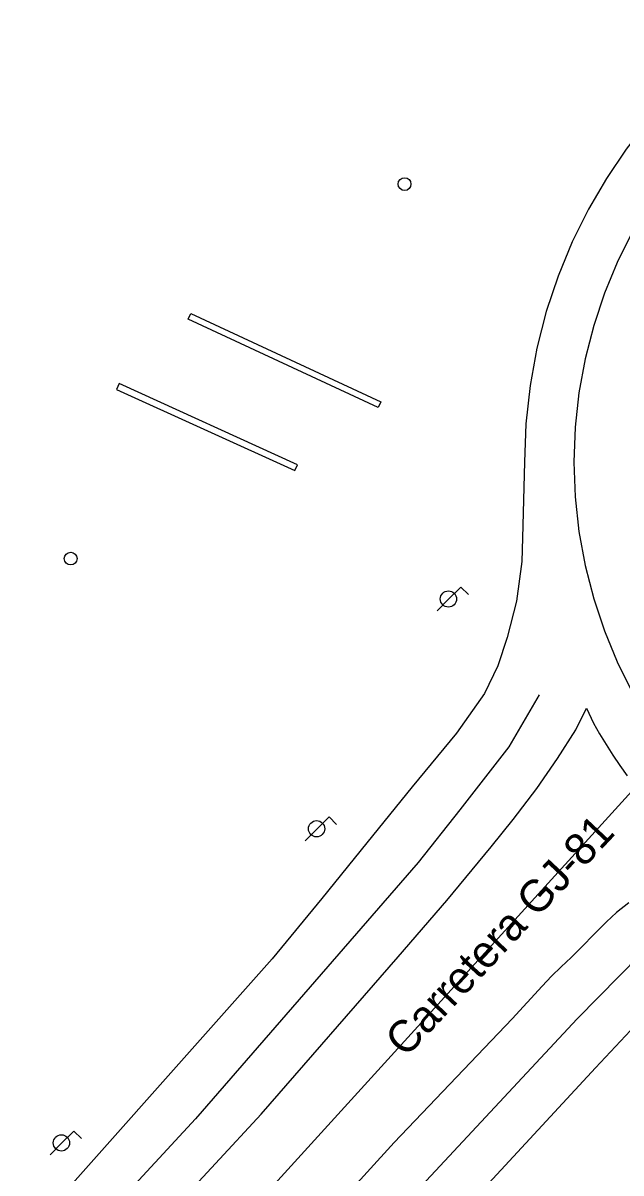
# Model space of a CAD drawing. Extents: x 282771 to 285132, y 4823109 to 4825496.
# Drawn here: x 283301 to 283347.9, y 4823498.7 to 4823588.9 of the extents above; entities that cross this region are included whole.
import ezdxf

# ---------------------------------------------------------------- set-up
doc = ezdxf.new("R2010")
doc.units = 0
for name, color, linetype in [('CALLE-EJE', 7, 'Continuous'), ('CALLE-TEXTO', 7, 'Continuous'), ('FAROLA', 7, 'Continuous'), ('POSTE', 7, 'Continuous'), ('PUENTE', 7, 'Continuous'), ('SENAL-VIARIA', 7, 'Continuous')]:
    doc.layers.add(name, color=color, linetype=linetype)

msp = doc.modelspace()

# ---------------------------------------------------------------- linework, layer by layer
at = {"layer": 'CALLE-EJE'}
msp.add_lwpolyline([(283294.286, 4823468.814), (283332.47, 4823510.781), (283376.815, 4823559.518)], dxfattribs=at)
at = {"layer": 'FAROLA'}
for p, q in [((283335.339, 4823544.653), (283334.399, 4823543.723)), ((283335.929, 4823544.063), (283335.339, 4823544.653)), ((283334.399, 4823543.723), (283333.469, 4823542.783)), ((283324.998, 4823526.639), (283324.058, 4823525.709)), ((283325.588, 4823526.049), (283324.998, 4823526.639)), ((283324.058, 4823525.709), (283323.128, 4823524.769)), ((283304.987, 4823502.009), (283304.047, 4823501.079)), ((283305.577, 4823501.419), (283304.987, 4823502.009)), ((283304.047, 4823501.079), (283303.117, 4823500.139))]:
    msp.add_line(p, q, dxfattribs=at)
for centre in [(283334.359, 4823543.723), (283324.018, 4823525.709), (283304.007, 4823501.079)]:
    msp.add_circle(centre, 0.637, dxfattribs=at)
at = {"layer": 'POSTE'}
for centre in [(283330.916, 4823576.246), (283304.736, 4823546.892)]:
    msp.add_circle(centre, 0.5, dxfattribs=at)
at = {"layer": 'PUENTE'}
for points in [[(283313.94, 4823565.663), (283314.151, 4823566.116), (283329.05, 4823559.184), (283328.839, 4823558.731), (283313.94, 4823565.663)], [(283322.527, 4823554.241), (283308.537, 4823560.611), (283308.33, 4823560.156), (283322.32, 4823553.786), (283322.527, 4823554.241)]]:
    msp.add_lwpolyline(points, dxfattribs=at)
at = {"layer": 'SENAL-VIARIA'}
for points in [[(283372.469, 4823595.074), (283369.988, 4823594.406), (283367.615, 4823593.61), (283365.357, 4823592.701), (283363.218, 4823591.693), (283361.199, 4823590.601), (283359.243, 4823589.398), (283357.301, 4823588.05), (283355.385, 4823586.549), (283353.509, 4823584.892), (283351.69, 4823583.078), (283349.946, 4823581.105), (283348.293, 4823578.977), (283346.75, 4823576.697), (283345.335, 4823574.274), (283344.066, 4823571.717), (283342.96, 4823569.039), (283342.032, 4823566.256), (283341.296, 4823563.385), (283340.761, 4823560.447), (283340.437, 4823557.462), (283340.329, 4823554.453), (283340.16, 4823548.516), (283340.112, 4823546.651)], [(283348.746, 4823572.435), (283347.595, 4823570.115), (283346.592, 4823567.686), (283345.75, 4823565.161), (283345.081, 4823562.556), (283344.597, 4823559.89), (283344.303, 4823557.183), (283344.204, 4823554.453), (283344.303, 4823551.724), (283344.597, 4823549.017), (283345.081, 4823546.351), (283345.75, 4823543.746), (283346.592, 4823541.221), (283347.595, 4823538.792), (283348.746, 4823536.472)], [(283340.112, 4823546.651), (283339.699, 4823543.549), (283338.965, 4823540.69), (283338.232, 4823538.492), (283337.189, 4823536.308), (283334.987, 4823533.194), (283331.528, 4823528.992), (283327.958, 4823524.617), (283324.42, 4823520.247), (283320.529, 4823515.51), (283299.222, 4823491.558)], [(283341.464, 4823536.218), (283339.084, 4823532.129), (283335.266, 4823527.186), (283331.987, 4823523.052), (283314.515, 4823502.966), (283301.821, 4823489.23)], [(283312.522, 4823495.601), (283319.666, 4823503.327), (283330.408, 4823515.656), (283334.241, 4823520.093), (283337.714, 4823524.294), (283339.434, 4823526.443), (283341.286, 4823528.858), (283342.907, 4823531.206), (283344.362, 4823533.455), (283345.189, 4823535.175), (283345.728, 4823533.99), (283346.218, 4823533.141), (283346.729, 4823532.302), (283347.261, 4823531.475), (283347.812, 4823530.659), (283348.384, 4823529.856)], [(283312.512, 4823476.827), (283329.041, 4823494.262), (283344.447, 4823510.799), (283349.412, 4823515.857), (283350.9, 4823517.038), (283352.107, 4823517.783), (283353.698, 4823518.707), (283355.495, 4823519.324), (283356.675, 4823519.555), (283358.395, 4823519.837)], [(283348.496, 4823519.895), (283347.537, 4823519.134), (283346.743, 4823518.407), (283345.806, 4823517.481), (283344.792, 4823516.422), (283343.985, 4823515.609), (283343.199, 4823514.888), (283342.444, 4823514.14), (283341.721, 4823513.367), (283339.368, 4823510.8), (283330.091, 4823501.104), (283319.772, 4823489.78)], [(283348.641, 4823509.904), (283345.883, 4823506.963), (283329.131, 4823488.856)]]:
    msp.add_lwpolyline(points, dxfattribs=at)

# ---------------------------------------------------------------- texts
at = {"layer": 'CALLE-TEXTO'}
msp.add_text('Carretera GJ-81', height=2.5, rotation=46.84037, dxfattribs=at).set_placement((283331.004, 4823507.7))

doc.saveas('drawing.dxf')
